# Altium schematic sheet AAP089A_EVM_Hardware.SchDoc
size Letter; Date: Not shown in title block; ApprovedBy: Not shown in title block; CheckedBy: Not shown in title block; Author: Not shown in title block; CompanyName: Not shown in title block; Engineer: Not shown in title block; Organization: Not shown in title block; Address1: Not shown in title block; Address2: Not shown in title block; Address3: Not shown in title block; Address4: Not shown in title block; DocumentNumber: 2; Revision: Use project parameter SCH_Rev; SheetNumber: 2; SheetTotal: 2; PageSetup: Record=PageOptions¦CenterHorizontal=True¦CenterVertical=True¦PrintScale=1.00¦XCorrection=1.00¦YCorrection=1.00¦PrintKind=0¦BorderSize=5000000¦LeftOffset=0¦BottomOffset=0¦Orientation=2¦PaperLength=1000¦PaperWidth=1000¦Scale=100¦PaperSource=15¦PrintQuality=600¦MediaType=1¦DitherType=10¦PaperKind=Letter¦PrintScaleMode=1
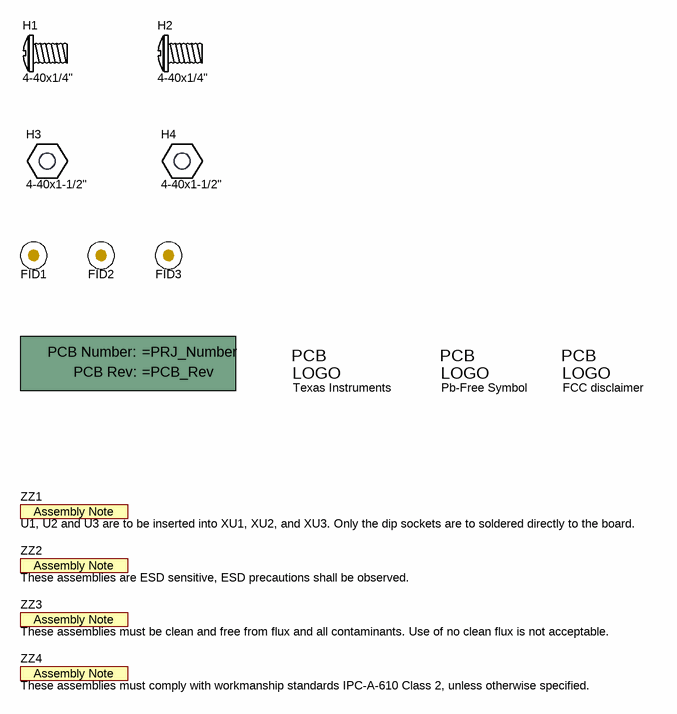
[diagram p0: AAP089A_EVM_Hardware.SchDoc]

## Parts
!PCB1  Printed Circuit Board  (value not drawn)  (mechanical)
FID1  Fiducial  [Fiducial10-20]  (value not drawn)
FID2  Fiducial  [Fiducial10-20]  (value not drawn)
FID3  Fiducial  [Fiducial10-20]  (value not drawn)
H1  4-40x1/4"  [B_F_PMSSS4400025PH]
H2  4-40x1/4"  [B_F_PMSSS4400025PH]
H3  4-40x1-1/2"  [Keystone_3483]
H4  4-40x1-1/2"  [Keystone_3483]
Logo1  Texas Instruments  [TI_Stacked_Overlay_Small]  (no BOM)
Logo2  Pb-Free Symbol  [Pb-Free_Overlay_Small]  (no BOM)
Logo3  FCC disclaimer  [FCC_disclaimer_stacked]  (no BOM)
ZZ1  U1, U2 and U3 are to be inserted into XU1, XU2, and XU3. Only the dip sockets are to soldered directly to the board.  [AssemblyNote]  (no BOM)
ZZ2  These assemblies are ESD sensitive, ESD precautions shall be observed.  [AssemblyNote]  (no BOM)
ZZ3  These assemblies must be clean and free from flux and all contaminants. Use of no clean flux is not acceptable.  [AssemblyNote]  (no BOM)
ZZ4  These assemblies must comply with workmanship standards IPC-A-610 Class 2, unless otherwise specified.  [AssemblyNote]  (no BOM)

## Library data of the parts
!PCB1 = PCB: Manufacturer: Any; SymbolCreator: a0412235
FID1-FID3 = Fiducial: Fiducial mark.  There is nothing to buy or mount.; SymbolCreator: codlsc
H1 H2 = PMSSS 440 0025 PH: MACHINE SCREW PAN PHILLIPS 4-40; Manufacturer: B&F Fastener Supply; CompType: Standoff; SymbolCreator: a0412235
H3 H4 = 3483: 1/4 Round Female Standoff, Alum, 1-1/2"; Manufacturer: Keystone; SymbolCreator: a0412235
Logo1 = TI_Logo: Texas Instrument Corporate Signature; SymbolCreator: codlsc
Logo2 = Pb-Free: SymbolCreator: a0412235
Logo3 = FCC_disclaimer: SymbolCreator: codlsc
ZZ1-ZZ4 = AssemblyNote: SymbolCreator: codlsc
